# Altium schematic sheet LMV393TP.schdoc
size 127 x 101 mm
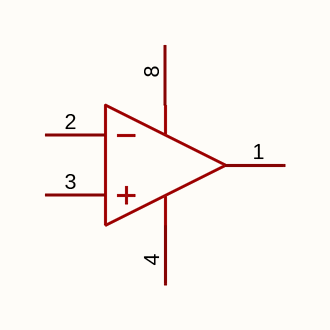
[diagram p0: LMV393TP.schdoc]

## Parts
U?  lmv393tp  [SOP-8_L4.9-W3.9-P1.27-LS6.0-BL]  (value not drawn)  (part A of 2)

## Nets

Not connected (* = marked no-connect by the designer): U? 1(OUT_A) 2(IN_A-) 3(IN_A+) 4(V-) 8(V+)

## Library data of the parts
U? = lmv393tp: 比较器数:双路;输入失调电压(Vos):800uV;输入偏置电流(Ib):2pA;轨到轨:-;; Manufacturer: TECH PUBLIC(台舟); AddInBom: yes; ModelId: 75c24a7891ee4dd6bdac16a7163ff87e; ModelName: SOP-8_L4.9-W3.9-P1.27-LS6.0-BL-1; ModelTransform: 192.913,236.22,0,0,0,0,-0.393,2.749,0; Number of Elements: 双路; Input Offset Voltage (Vos): 800uV; Input Bias Current (Ib): 2pA; Propagation Delay Time: 460ns; Supply Voltage: 1.8V~5.5V; Output Type: 开漏; Supply Current: 50uA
